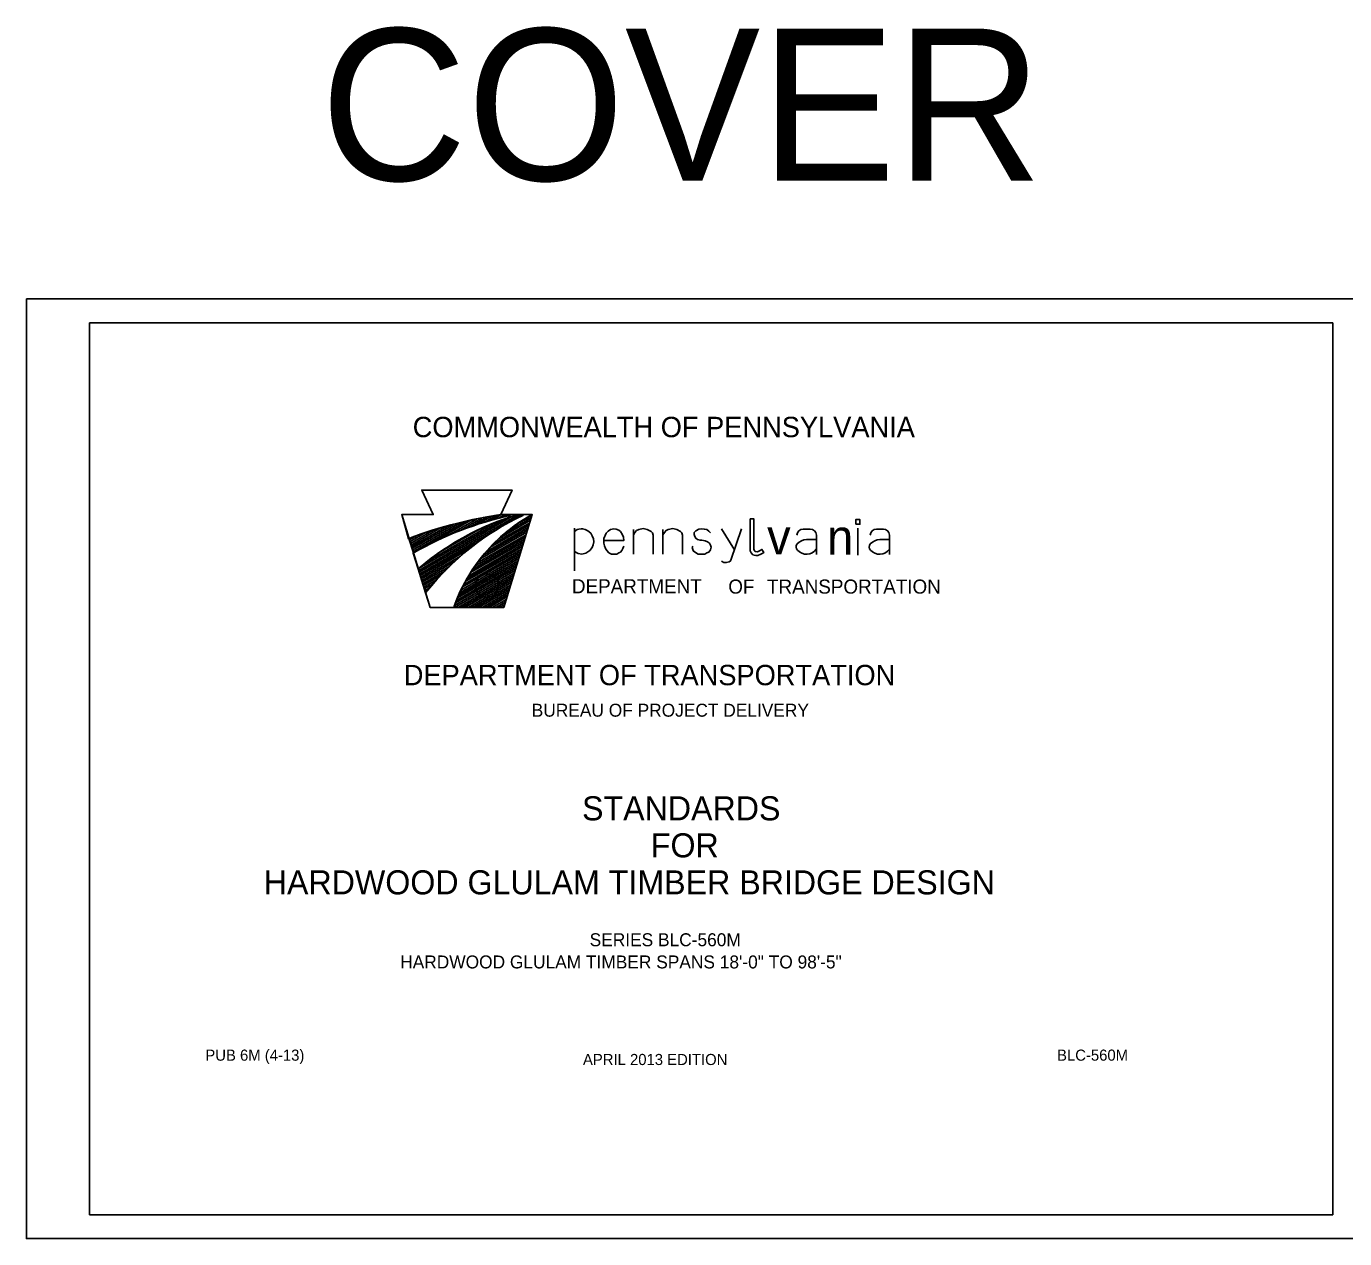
# Model space of a CAD drawing. Extents: x 637594 to 640253, y 297247 to 298435.
# Drawn here: x 637594 to 638428, y 297247 to 298014 of the extents above; entities that cross this region are included whole.
import ezdxf

# ---------------------------------------------------------------- set-up
doc = ezdxf.new("R2010")
doc.units = 0
for name, color, linetype in [('1', 7, 'Continuous'), ('2', 7, 'Continuous'), ('4', 7, 'Continuous'), ('PLT-BNDY', 7, 'Continuous')]:
    doc.layers.add(name, color=color, linetype=linetype)

msp = doc.modelspace()

# ---------------------------------------------------------------- linework, layer by layer
at = {"layer": '1'}
for p, q in [((637851.67, 297705.17), (637844.47, 297720.7)), ((637844.47, 297720.7), (637901.58, 297720.7)), ((637901.58, 297720.7), (637894.37, 297705.17)), ((637849.74, 297646.45), (637831.76, 297705.17)), ((637831.76, 297705.17), (637851.67, 297705.17)), ((637894.37, 297705.17), (637914.28, 297705.17)), ((637914.28, 297705.17), (637896.3, 297646.45)), ((638085.64, 297696.03), (638090.01, 297696.03)), ((638120.26, 297696.55), (638120.26, 297679.55)), ((638131.94, 297696.03), (638136.3, 297696.03)), ((638093.94, 297689.37), (638087.81, 297689.37)), ((638093.94, 297692.23), (638093.94, 297679.98)), ((638140.24, 297689.37), (638134.1, 297689.37)), ((638140.24, 297692.23), (638140.24, 297679.98)), ((637896.3, 297646.45), (637849.74, 297646.45))]:
    msp.add_line(p, q, dxfattribs=at)
for points in [[(637894.37, 297705.17), (637901.58, 297720.7), (637844.47, 297720.7), (637851.67, 297705.17), (637831.76, 297705.17), (637835.97, 297689.92), (637843.98, 297692.94), (637850.95, 297695.21), (637856.7, 297696.95), (637862.79, 297698.6), (637867.32, 297699.82), (637876.63, 297701.98), (637885.86, 297703.72), (637891.53, 297704.68)], [(637894.37, 297705.17), (637890.4, 297704.52), (637885.78, 297703.65), (637880.3, 297702.61), (637875.59, 297701.56), (637870.19, 297700.43), (637863.1, 297698.58), (637855.91, 297696.6), (637849.73, 297694.68), (637843.37, 297692.59), (637838.24, 297690.68), (637836.22, 297689.98), (637839.25, 297680.89), (637843.9, 297683.71), (637848.95, 297686.32), (637853.04, 297688.33), (637857.83, 297690.68), (637862.71, 297692.77), (637868.02, 297694.95), (637872.2, 297696.51), (637877.34, 297698.34), (637882.3, 297699.91), (637887.96, 297701.56), (637892.66, 297702.96), (637897.8, 297704.09), (637901.37, 297705.22)], [(637901.37, 297705.22), (637892.05, 297702.78), (637879.51, 297699.04), (637869.07, 297695.37), (637859.75, 297691.53), (637849.47, 297686.67), (637841.37, 297682.23), (637839, 297680.84), (637842.27, 297670.86), (637846.94, 297674.92), (637850.34, 297677.53), (637854.61, 297680.58), (637858.18, 297683.02), (637862.38, 297685.71), (637867.35, 297688.68), (637873.5, 297692.25), (637879.08, 297695.03), (637885.43, 297697.99), (637888.92, 297699.3), (637893.97, 297701.39), (637900.15, 297703.48), (637905.26, 297705.17)], [(637905.26, 297705.17), (637899.76, 297703.33), (637895.14, 297701.76), (637889.66, 297699.58), (637884.08, 297697.32), (637878.42, 297694.71), (637872.15, 297691.4), (637865.8, 297687.83), (637860.22, 297684.34), (637855.09, 297680.95), (637849.6, 297676.85), (637845.68, 297673.81), (637842.27, 297670.86), (637846.77, 297655.76), (637852.3, 297662.27), (637857.18, 297667.62), (637861.7, 297672.15), (637867.02, 297677.29), (637871.54, 297681.12), (637876.68, 297685.3), (637881.73, 297689.22), (637886.26, 297692.27), (637891.31, 297695.49), (637896.36, 297698.45), (637900.02, 297700.63), (637904.46, 297703.07), (637909.21, 297705.22)], [(637909.21, 297705.22), (637904.92, 297703.34), (637898.65, 297699.95), (637890.92, 297695.21), (637882.12, 297689.37), (637874.72, 297683.8), (637870.63, 297680.49), (637863.84, 297674.31), (637859.66, 297670.13), (637854.17, 297664.29), (637850.6, 297660.2), (637846.77, 297655.76), (637849.74, 297646.45), (637864.71, 297646.44), (637865.67, 297649.05), (637868.54, 297656.11), (637870.37, 297659.77), (637873.55, 297665.62), (637876.38, 297670.3), (637880.3, 297675.79), (637884.21, 297680.58), (637889.27, 297686.15), (637894.32, 297691.11), (637898.76, 297694.68), (637902.85, 297697.99), (637906.86, 297700.69), (637911.38, 297703.48), (637914.28, 297705.17)], [(637914.28, 297705.17), (637910.9, 297703.15), (637907.16, 297700.8), (637902.98, 297697.93), (637898.1, 297694.18), (637894.19, 297690.96), (637891.14, 297687.91), (637887.39, 297683.91), (637883.13, 297679.21), (637879.56, 297674.76), (637876.42, 297670.24), (637873.72, 297665.88), (637871.72, 297662.31), (637869.02, 297657.17), (637866.23, 297650.3), (637864.71, 297646.44), (637896.3, 297646.45)], [(638052.1, 297702.4), (638052.1, 297682.19), (638052.63, 297681), (638053.87, 297679.79), (638054.68, 297679.48), (638055.6, 297679.36), (638056.97, 297679.38), (638058.94, 297680.14), (638059.77, 297680.57), (638060.76, 297681.23), (638059.49, 297683.15), (638058.05, 297682.19), (638056.81, 297681.67), (638055.34, 297681.75), (638054.68, 297682.62), (638054.48, 297683.32), (638054.48, 297702.4)], [(638118.8, 297699.01), (638121.48, 297699.01), (638121.48, 297701.99), (638118.8, 297701.99)]]:
    msp.add_lwpolyline(points, close=True, dxfattribs=at)
msp.add_circle((637885.65, 297660.31), 7.39, dxfattribs=at)
for centre, radius, start, end in [((637940.81, 297407.95), 300.83, 98.88028, 110.39616), ((637944.89, 297499.19), 210.13, 102.171, 120.23933), ((637954.1, 297540.44), 171.8, 106.62978, 130.61172), ((637981.9, 297549.53), 171.7, 115.37242, 141.71648), ((637965.96, 297611.14), 107.3, 118.79798, 160.36629)]:
    msp.add_arc(centre, radius, start, end, dxfattribs=at)
for centre, major_axis, start_param, end_param in [((638085.64, 297691.92), (0, -4.11), 3.141593, 4.64997), ((638090.01, 297691.92), (0, 4.11), 4.789654, 6.283185), ((638131.94, 297691.92), (0, -4.11), 3.141593, 4.64997), ((638136.3, 297691.92), (0, 4.11), 4.789654, 6.283185), ((638083.91, 297684.73), (0, -2.91), 4.014, 5.498069), ((638088.18, 297679.98), (0, 9.4), 0.041523, 0.789828), ((638130.2, 297684.73), (0, -2.91), 4.014, 5.498069), ((638134.48, 297679.98), (0, 9.4), 0.041523, 0.789828), ((638087.66, 297688.28), (0, 8.19), 2.325877, 4.056693), ((638133.96, 297688.28), (0, 8.19), 2.325877, 4.056693)]:
    msp.add_ellipse(centre, major_axis=major_axis, ratio=0.96098, start_param=start_param, end_param=end_param, dxfattribs=at)
at = {"layer": '2'}
for p, q in [((637634.46, 297262.46), (637634.46, 297826.46)), ((637634.46, 297826.46), (638420.46, 297826.46)), ((638420.46, 297826.46), (638420.46, 297262.46)), ((637842.55, 297669.91), (637901.35, 297703.86)), ((637842.74, 297671.27), (637896.14, 297702.1)), ((637842.87, 297668.85), (637905.79, 297705.17)), ((637850.23, 297686.95), (637875.51, 297701.55)), ((637861.77, 297692.37), (637879.01, 297702.32)), ((637869.09, 297695.35), (637882.34, 297703)), ((637874.99, 297697.51), (637885.57, 297703.61)), ((637880.12, 297699.22), (637888.78, 297704.22)), ((637884.68, 297700.6), (637891.89, 297704.77)), ((637889.07, 297701.89), (637894.76, 297705.18)), ((637893.29, 297690.06), (637913.16, 297701.54)), ((637893.32, 297703.1), (637896.94, 297705.19)), ((637896.82, 297703.87), (637899.13, 297705.21)), ((637897.73, 297693.88), (637913.63, 297703.05)), ((637901.07, 297701.2), (637908, 297705.2)), ((637901.24, 297705.18), (637901.31, 297705.22)), ((637905.04, 297699.34), (637914.09, 297704.57)), ((637836.89, 297687.98), (637846.88, 297693.75)), ((637837.24, 297686.93), (637851.74, 297695.31)), ((637837.66, 297685.93), (637856.35, 297696.72)), ((637837.98, 297684.87), (637860.48, 297697.86)), ((637838.28, 297683.8), (637864.55, 297698.96)), ((637838.63, 297682.75), (637868.49, 297699.99)), ((637838.98, 297681.7), (637872.11, 297700.83)), ((637843.19, 297667.79), (637898.36, 297699.64)), ((637847.71, 297675.39), (637889.54, 297699.53)), ((637854.75, 297680.7), (637881.37, 297696.07)), ((637881.26, 297676.88), (637910.84, 297693.97)), ((637883.13, 297679.21), (637911.31, 297695.48)), ((637885.51, 297681.83), (637911.77, 297696.99)), ((637887.92, 297684.47), (637912.24, 297698.51)), ((637890.45, 297687.18), (637912.7, 297700.02)), ((637836.68, 297689.11), (637841.53, 297691.91)), ((637843.5, 297666.72), (637879.58, 297687.55)), ((637873.03, 297664.65), (637908.06, 297684.88)), ((637874.12, 297666.53), (637908.53, 297686.39)), ((637875.33, 297668.47), (637908.99, 297687.91)), ((637876.55, 297670.42), (637909.45, 297689.42)), ((637877.99, 297672.5), (637909.92, 297690.94)), ((637879.43, 297674.58), (637910.38, 297692.45)), ((637843.82, 297665.66), (637873.84, 297682.99)), ((637844.14, 297664.59), (637868.92, 297678.9)), ((637868.45, 297655.77), (637905.74, 297677.3)), ((637869.15, 297657.42), (637906.21, 297678.82)), ((637870.09, 297659.21), (637906.67, 297680.33)), ((637871.03, 297661), (637907.14, 297681.85)), ((637872, 297662.81), (637907.6, 297683.36)), ((637844.46, 297663.53), (637865.13, 297675.47)), ((637844.77, 297662.47), (637861.93, 297672.37)), ((637845.09, 297661.4), (637858.96, 297669.41)), ((637865.19, 297647.65), (637903.43, 297669.73)), ((637865.25, 297646.44), (637902.96, 297668.21)), ((637865.83, 297649.27), (637903.89, 297671.24)), ((637866.47, 297650.89), (637904.35, 297672.76)), ((637867.13, 297652.52), (637904.82, 297674.27)), ((637867.79, 297654.14), (637905.28, 297675.79)), ((637845.41, 297660.34), (637856.23, 297666.59)), ((637845.72, 297659.27), (637853.84, 297663.96)), ((637846.04, 297658.21), (637851.56, 297661.39)), ((637867.41, 297646.44), (637902.5, 297666.7)), ((637869.57, 297646.44), (637902.04, 297665.18)), ((637871.74, 297646.44), (637901.57, 297663.67)), ((637873.9, 297646.44), (637901.11, 297662.16)), ((637876.06, 297646.45), (637900.64, 297660.64)), ((637846.36, 297657.15), (637849.48, 297658.95)), ((637846.67, 297656.08), (637847.4, 297656.5)), ((637878.22, 297646.45), (637900.18, 297659.13)), ((637880.38, 297646.45), (637899.72, 297657.61)), ((637882.54, 297646.45), (637899.25, 297656.1)), ((637884.7, 297646.45), (637898.79, 297654.58)), ((637886.86, 297646.45), (637898.33, 297653.07)), ((637889.02, 297646.45), (637897.86, 297651.55)), ((637891.19, 297646.45), (637897.4, 297650.04)), ((637893.35, 297646.45), (637896.94, 297648.52)), ((637895.51, 297646.45), (637896.47, 297647.01)), ((638420.46, 297262.46), (638420.46, 297382.46)), ((638420.46, 297262.46), (637634.46, 297262.46)), ((638220.46, 297262.46), (638420.46, 297262.46))]:
    msp.add_line(p, q, dxfattribs=at)
for points in [[(637941, 297696.52), (637941, 297669.5)], [(637941, 297694.41), (637942.76, 297695.64), (637943.78, 297695.99), (637945.25, 297696.17), (637946.13, 297696.17), (637947.74, 297695.82), (637949.5, 297694.94), (637951.26, 297693.36), (637952.28, 297691.78), (637953.01, 297689.85), (637953.16, 297687.92), (637952.87, 297685.99), (637952.14, 297684.41), (637950.67, 297682.49), (637948.18, 297680.73), (637945.69, 297680.2), (637943.34, 297680.56), (637942.02, 297681.26), (637941, 297681.96)], [(637959.61, 297688.8), (637972.22, 297688.8), (637971.92, 297690.9), (637971.19, 297692.83), (637970.16, 297694.41), (637969.14, 297695.29), (637967.38, 297695.99), (637965.91, 297696.17), (637963.86, 297695.82), (637962.4, 297694.76), (637961.08, 297693.36), (637959.61, 297690.03), (637959.61, 297687.05), (637960.05, 297685.47), (637960.64, 297683.71), (637961.52, 297682.49), (637962.69, 297681.08), (637964.45, 297680.2), (637966.21, 297680.2), (637967.82, 297680.2), (637968.99, 297680.91), (637970.02, 297681.43), (637970.9, 297682.49), (637971.48, 297683.71), (637972.22, 297685.29)], [(637978.23, 297692.31), (637979.25, 297693.88), (637980.28, 297695.11), (637981.6, 297695.82), (637984.53, 297696.34), (637987.02, 297695.82), (637989.51, 297694.41), (637990.24, 297693.53), (637990.68, 297692.13), (637990.68, 297680.2)], [(637978.23, 297680.2), (637978.23, 297695.82)], [(637996.84, 297692.31), (637997.87, 297693.88), (637998.89, 297695.11), (638000.21, 297695.82), (638003.14, 297696.34), (638005.63, 297695.82), (638008.13, 297694.41), (638008.86, 297693.53), (638009.3, 297692.13), (638009.3, 297680.2)], [(637996.84, 297680.2), (637996.84, 297695.82)], [(638027.03, 297693.71), (638026.01, 297694.59), (638024.69, 297695.64), (638023.07, 297695.99), (638021.46, 297696.17), (638019.56, 297695.99), (638017.8, 297694.94), (638016.77, 297693.88), (638016.63, 297692.48), (638017.07, 297691.26), (638017.65, 297690.2), (638018.83, 297689.32), (638020.44, 297688.97), (638021.61, 297688.97), (638023.66, 297688.62), (638025.13, 297687.92), (638026.3, 297687.05), (638027.03, 297685.82), (638027.47, 297684.59), (638027.03, 297682.84), (638025.86, 297681.43), (638024.69, 297680.91), (638023.37, 297680.2), (638021.46, 297680.2), (638019.12, 297680.2), (638016.33, 297681.96), (638015.75, 297683.19), (638015.45, 297684.41), (638015.75, 297685.29)], [(638046.67, 297696.17), (638039.93, 297676.35), (638039.49, 297675.64), (638038.76, 297675.29), (638037, 297674.77), (638035.53, 297674.77), (638034.07, 297675.64)], [(638042.13, 297682.84), (638034.07, 297696.17)]]:
    msp.add_lwpolyline(points, dxfattribs=at)
at = {"layer": 'PLT-BNDY'}
msp.add_lwpolyline([(637594.46, 297841.46), (638435.46, 297841.46), (638435.46, 297247.46), (637594.46, 297247.46)], close=True, dxfattribs=at)

# ---------------------------------------------------------------- texts
at = {"layer": '1'}
for s, p in [('v', (638062.82, 297680)), ('n', (638100.72, 297679.76))]:
    msp.add_text(s, height=22.28, dxfattribs=at).set_placement(p)
at = {"layer": '2'}
msp.add_text('DEPARTMENT', height=8.91, dxfattribs=at).set_placement((637939.4, 297655.39))
for s, height, p in [('OF', 8.91, (638038.26, 297655.19)), ('TRANSPORTATION', 8.9103, (638062.73, 297655.19))]:
    msp.add_text(s, height=height, rotation=360, dxfattribs=at).set_placement(p)
at = {"layer": '4'}
for s, height, p in [('COVER', 96, (637780.31, 297916.35)), ('COMMONWEALTH OF PENNSYLVANIA', 12.8716, (637838.73, 297754.09)), ('DEPARTMENT OF TRANSPORTATION', 12.8716, (637833.06, 297597.29)), ('BUREAU OF PROJECT DELIVERY', 8.191, (637913.98, 297577.4)), ('STANDARDS', 15.212, (637945.79, 297511.87)), ('FOR', 15.212, (637989.29, 297488.47)), ('HARDWOOD GLULAM TIMBER BRIDGE DESIGN', 15.2119, (637744.55, 297465.07)), ('SERIES BLC-560M', 8.191, (637950.61, 297432.3)), ('HARDWOOD GLULAM TIMBER SPANS 18\'-0" TO 98\'-5"', 8.191, (637830.82, 297418.26)), ('PUB 6M (4-13)', 7.0209, (637707.63, 297359.93)), ('APRIL 2013 EDITION', 7.0209, (637946.37, 297357.19)), ('BLC-560M', 7.021, (638246.14, 297359.93))]:
    msp.add_text(s, height=height, dxfattribs=at).set_placement(p)

doc.saveas('drawing.dxf')
